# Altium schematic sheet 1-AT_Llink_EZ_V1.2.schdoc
size 307 x 223 mm
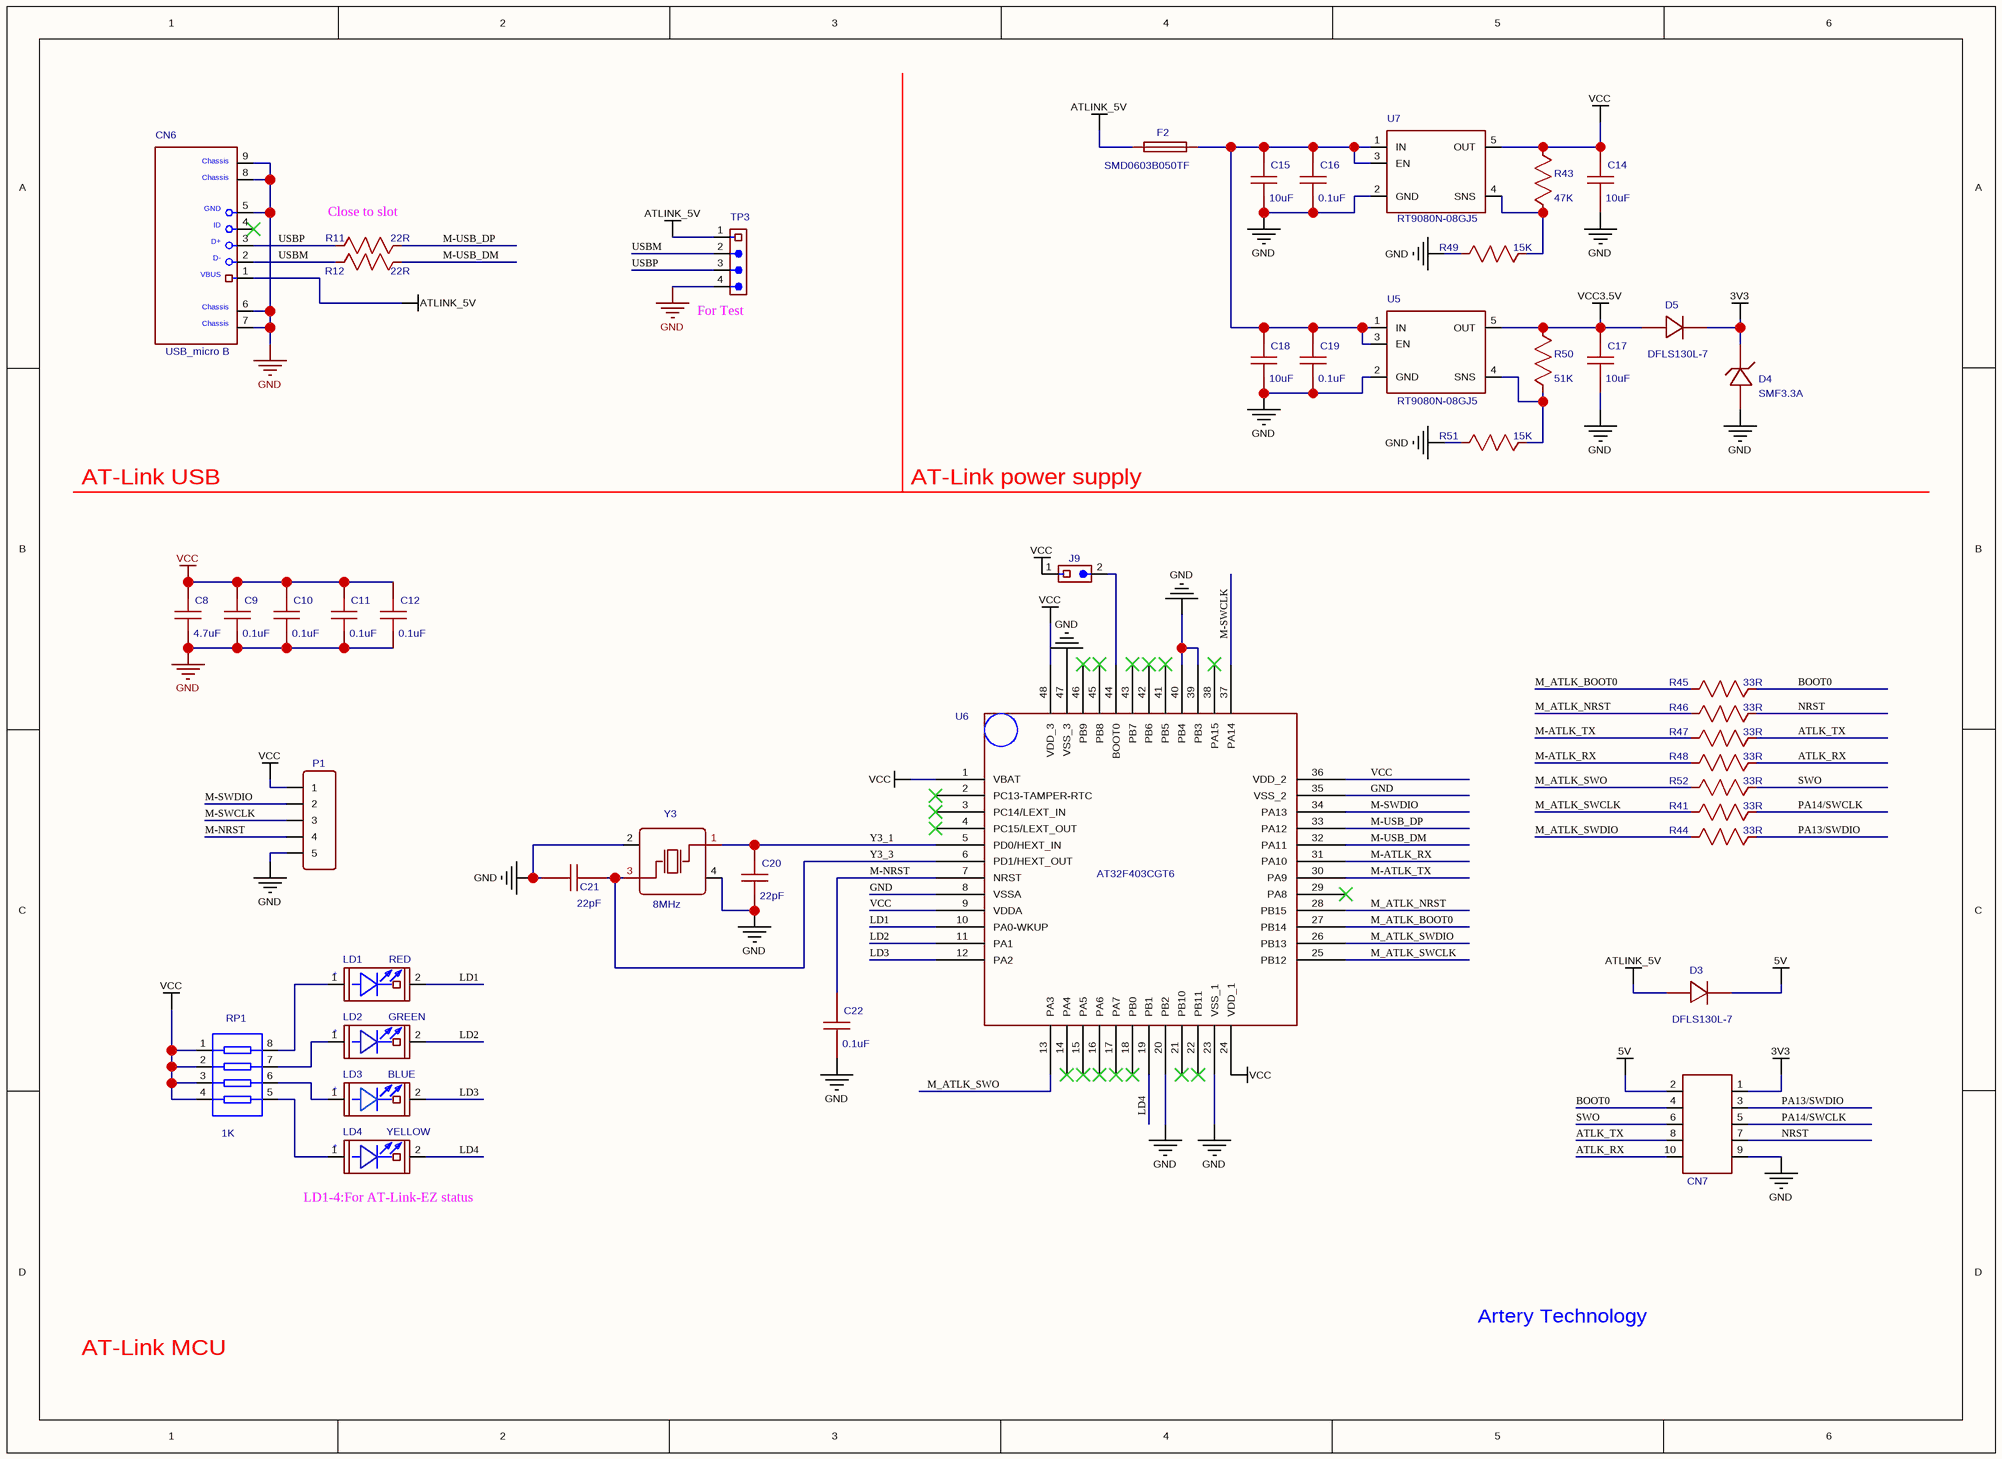
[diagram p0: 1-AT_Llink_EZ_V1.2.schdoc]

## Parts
C8  4.7uF  [0603_C-M]
C9  0.1uF  [0603_C-M]
C10  0.1uF  [0603_C-M]
C11  0.1uF  [0603_C-M]
C12  0.1uF  [0603_C-M]
C14  10uF  [0603_C-M]
C15  10uF  [0603_C-M]
C16  0.1uF  [0603_C-M]
C17  10uF  [0603_C-M]
C18  10uF  [0603_C-M]
C19  0.1uF  [0603_C-M]
C20  22pF  [0603_C-M]
C21  22pF  [0603_C-M]
C22  0.1uF  [0603_C-M]
CN6  USB_micro B  [USB_MIC_DIP]
CN7  直插简易牛角2.54mm，2x5P  [HDR2X5]  (value not drawn)
D3  DFLS130L-7  [POWERDI-123_L2.8-W1.8-LS3.7-RD]
D4  SMF3.3A  [SOD-123_L2.8-W1.8-LS3.7-RD]
D5  DFLS130L-7  [POWERDI-123_L2.8-W1.8-LS3.7-RD]
F2  SMD0603B050TF  [R0603]
J9  Jumper 1x2P  [HDR1X2]  (value not drawn)
LD1  RED  [LED0603]
LD2  GREEN  [LED0603]
LD3  BLUE  [LED0603]
LD4  YELLOW  [LED0603]
P1  HDR-M-2.54_1x5  [HDR-M-2.54_1X5]  (value not drawn)
R11  22R  [0603_R-M]
R12  22R  [0603_R-M]
R41  33R  [0603_R-M]
R43  47K  [0603_R-M]
R44  33R  [0603_R-M]
R45  33R  [0603_R-M]
R46  33R  [0603_R-M]
R47  33R  [0603_R-M]
R48  33R  [0603_R-M]
R49  15K  [0603_R-M]
R50  51K  [0603_R-M]
R51  15K  [0603_R-M]
R52  33R  [0603_R-M]
RP1  1K  [0603*4,8P4R]
TP3  1X4P_2.54F  [HDR1X4 - TOP]  (value not drawn)
U5  RT9080N-08GJ5  [SOT-23-5]
U6  AT32F403CGT6  [LQFP48 - 2]
U7  RT9080N-08GJ5  [SOT-23-5]
Y3  8MHz  [OSC-SMD_4P-L5.0-W3.2-BL]

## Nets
3V3: CN7.1 D4.1 D5.1
5V: CN7.2 D3.1
ATLINK_5V: CN6.1(VBUS) D3.2 F2.1 TP3.1
GND: C8.2 C9.2 C10.2 C11.2 C12.2 C14.2 C15.2 C16.2 C17.2 C18.2 C19.2 C20.2 C21.1 C22.2 CN6.5(GND) CN6.6 CN6.7 CN6.8 CN6.9 CN7.9 D4.2 P1.5 R49.2 R51.2 TP3.4 U5.2(GND) U6.8(VSSA) U6.20(PB2) U6.23(VSS_1) U6.35(VSS_2) U6.39(PB3) U6.40(PB4) U6.47(VSS_3) U7.2(GND) Y3.2(GND) Y3.4(GND)
VCC: C8.1 C9.1 C10.1 C11.1 C12.1 C14.1 J9.1 P1.1 R43.2 RP1.1 RP1.2 RP1.3 RP1.4 U6.1(VBAT) U6.9(VDDA) U6.24(VDD_1) U6.36(VDD_2) U6.48(VDD_3) U7.5(OUT)
VCC3.5V: C17.1 D5.2 R50.2 U5.5(OUT)
ATLK_RX: CN7.10 R48.1
ATLK_TX: CN7.8 R47.1
BOOT0: CN7.4 R45.1
LD1: LD1.2(CATHODE) U6.10(PA0-WKUP)
LD2: LD2.2(CATHODE) U6.11(PA1)
LD3: LD3.2(CATHODE) U6.12(PA2)
LD4: LD4.2(CATHODE) U6.19(PB1)
M-ATLK_RX: R48.2 U6.31(PA10)
M-ATLK_TX: R47.2 U6.30(PA9)
M-NRST: C22.1 P1.4 U6.7(NRST)
M-SWCLK: P1.3 U6.37(PA14)
M-SWDIO: P1.2 U6.34(PA13)
M-USB_DM: R12.2 U6.32(PA11)
M-USB_DP: R11.2 U6.33(PA12)
M_ATLK_BOOT0: R45.2 U6.27(PB14)
M_ATLK_NRST: R46.2 U6.28(PB15)
M_ATLK_SWCLK: R41.2 U6.25(PB12)
M_ATLK_SWDIO: R44.2 U6.26(PB13)
M_ATLK_SWO: R52.2 U6.13(PA3)
NRST: CN7.7 R46.1
PA13/SWDIO: CN7.3 R44.1
PA14/SWCLK: CN7.5 R41.1
SWO: CN7.6 R52.1
USBM: CN6.2(D-) R12.1 TP3.2
USBP: CN6.3(D+) R11.1 TP3.3
Y3_1: C20.1 U6.5(PD0/HEXT_IN) Y3.1(OSC1)
Y3_3: C21.2 U6.6(PD1/HEXT_OUT) Y3.3(OSC2)
NetC15_1: C15.1 C16.1 C18.1 C19.1 F2.2 U5.1(IN) U5.3(EN) U7.1(IN) U7.3(EN)
NetJ9_2: J9.2 U6.44(BOOT0)
NetLD1_1: LD1.1(ANODE) RP1.8
NetLD2_1: LD2.1(ANODE) RP1.7
NetLD3_1: LD3.1(ANODE) RP1.6
NetLD4_1: LD4.1(ANODE) RP1.5
NetR43_1: R43.1 R49.1 U7.4(SNS)
NetR50_1: R50.1 R51.1 U5.4(SNS)

Not connected (* = marked no-connect by the designer): CN6 4(ID)*; U6 2(PC13-TAMPER-RTC)* 3(PC14/LEXT_IN)* 4(PC15/LEXT_OUT)* 14(PA4)* 15(PA5)* 16(PA6)* 17(PA7)* 18(PB0)* 21(PB10)* 22(PB11)* 29(PA8)* 38(PA15)* 41(PB5)* 42(PB6)* 43(PB7)* 45(PB8)* 46(PB9)*

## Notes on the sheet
- Close to slot
- (near TP3) For Test
- AT-Link USB
- AT-Link power supply
- (near LD4) LD1-4:For AT-Link-EZ status
- Artery Technology
- AT-Link MCU

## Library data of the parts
C8 = 4.7uF: nameAlias: Value(F); Contributor: LCEDA_Lib
C9-C12 C16 C19 C22 = 0.1uF: nameAlias: Value(F); Contributor: LCEDA_Lib
C14 C15 C17 C18 = 10uF: nameAlias: Value(F); Contributor: LCEDA_Lib
C20 C21 = 22pF: nameAlias: Value(F); Contributor: LCEDA_Lib
D3 D5 = DFLS130L-7: BOM_Manufacturer: Diodes Incorporated; Contributor: LCSC; BOM_Paste Type: expand
D4 = SMF3.3A: BOM_Manufacturer: DOWO; Contributor: LCSC; BOM_Paste Type: expand
F2 = SMD0603B050TF: BOM_Manufacturer: Brightking Elec (TAIWAN); BOM_Manufacturer Part: SMD0603B035TF; Contributor: LCSC; BOM_Paste Type: expand
J9 = Jumper 1x2P: Contributor: twb17
P1 = HDR-M-2.54_1x5: Contributor: LCEDA_Lib
R11 R12 = 22R: nameAlias: Value(Ω); Contributor: LCEDA_Lib
R41 R44-R48 R52 = 33R: nameAlias: Value(Ω); Contributor: LCEDA_Lib
R43 = 47K: nameAlias: Value(Ω); Contributor: LCEDA_Lib
R49 R51 = 15K: nameAlias: Value(Ω); Contributor: LCEDA_Lib
R50 = 51K: nameAlias: Value(Ω); Contributor: LCEDA_Lib
RP1 = 1K: Contributor: twb17
Y3 = 8MHz: BOM_Manufacturer: TAE; BOM_Manufacturer Part: SMD-5032_4P8M20pf20ppm; nameAlias: Frequency; Contributor: LCSC; BOM_Paste Type: recommend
